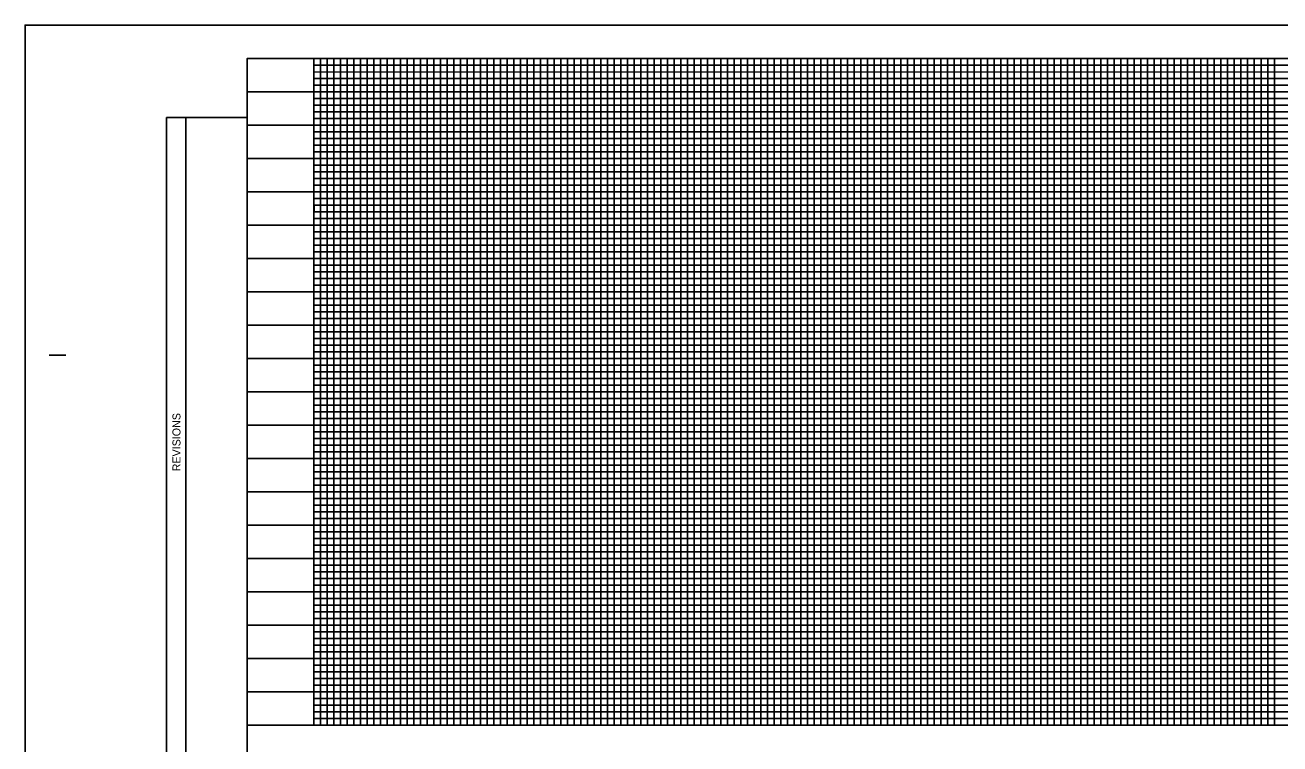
# Model space of a CAD drawing. Extents: x 2431000 to 2534000, y 645879 to 714000.
# Drawn here: x 2466807 to 2467748, y 669403 to 669942 of the extents above; entities that cross this region are included whole.
import ezdxf

# ---------------------------------------------------------------- set-up
doc = ezdxf.new("R2010")
doc.units = 0
for name, color, linetype in [('Prop Dimension', 7, 'Continuous'), ('Prop Shade Light', 7, 'Continuous'), ('Sheet Cross Section CELL', 7, 'Continuous'), ('Sheet Cross Section Grid Major CELL', 7, 'Continuous'), ('Sheet Cross Section Grid Middle CELL', 7, 'Continuous'), ('Sheet North Arrow Point CELL', 7, 'Continuous'), ('Sheet Plan And Profile CELL', 7, 'Continuous')]:
    doc.layers.add(name, color=color, linetype=linetype)

msp = doc.modelspace()

# ---------------------------------------------------------------- linework, layer by layer
at = {"layer": 'Prop Dimension'}
msp.add_lwpolyline([(2466807.25, 668842.06), (2468490.75, 668842.06), (2468490.75, 669942.06), (2466807.25, 669942.06)], close=True, dxfattribs=at)
at = {"layer": 'Prop Shade Light'}
for p, q in [((2466913.23, 669382.06), (2466913.23, 669872.71)), ((2466973.77, 669872.71), (2466913.23, 669872.71)), ((2466927.77, 669382.06), (2466927.77, 669872.72))]:
    msp.add_line(p, q, dxfattribs=at)
at = {"layer": 'Sheet Cross Section CELL'}
for p, q in [((2467023.75, 669912.06), (2468173.75, 669912.06)), ((2467023.75, 669907.06), (2467023.75, 669907.06)), ((2468173.75, 669907.03), (2467023.75, 669906.71)), ((2467023.75, 669902.06), (2468173.75, 669902.06)), ((2468173.75, 669782.06), (2467023.75, 669782.06)), ((2468423.75, 669777.06), (2467023.75, 669777.06)), ((2468423.75, 669772.06), (2467023.75, 669772.06)), ((2467023.75, 669762.06), (2468423.75, 669762.06)), ((2468423.75, 669757.06), (2467023.75, 669757.06)), ((2467023.75, 669752.06), (2468423.75, 669752.06)), ((2468423.75, 669732.06), (2467023.75, 669732.06)), ((2467023.75, 669727.06), (2468423.75, 669727.06)), ((2468423.75, 669707.06), (2467023.75, 669707.06)), ((2467023.75, 669702.06), (2468423.75, 669702.06)), ((2468423.75, 669682.06), (2467023.75, 669682.06)), ((2467023.75, 669677.06), (2468423.75, 669677.06)), ((2468423.75, 669672.06), (2467023.75, 669672.06)), ((2467023.75, 669662.06), (2468423.75, 669662.06)), ((2468423.75, 669657.06), (2467023.75, 669657.06)), ((2467023.75, 669652.06), (2468423.75, 669652.06)), ((2468423.75, 669647.06), (2467023.75, 669647.06)), ((2467023.75, 669637.06), (2468423.75, 669637.06)), ((2468423.75, 669632.06), (2467023.75, 669632.06)), ((2467023.75, 669627.06), (2468423.75, 669627.06)), ((2468423.75, 669622.06), (2467023.75, 669622.06)), ((2467023.75, 669612.06), (2468423.75, 669612.06)), ((2468423.75, 669607.06), (2467023.75, 669607.06)), ((2467023.75, 669602.06), (2468423.75, 669602.06)), ((2468423.75, 669597.06), (2467023.75, 669597.06)), ((2467023.75, 669587.06), (2468423.75, 669587.06)), ((2468423.75, 669582.06), (2467023.75, 669582.06)), ((2467023.75, 669577.06), (2468423.75, 669577.06)), ((2468423.75, 669572.06), (2467023.75, 669572.06)), ((2467023.75, 669562.06), (2468423.75, 669562.06)), ((2468423.75, 669557.06), (2467023.75, 669557.06)), ((2467023.75, 669552.06), (2468423.75, 669552.06)), ((2468423.75, 669547.06), (2467023.75, 669547.06)), ((2467023.75, 669537.06), (2468423.75, 669537.06)), ((2468423.75, 669532.06), (2467023.75, 669532.06)), ((2468423.75, 669527.06), (2467023.75, 669527.06)), ((2468423.75, 669522.06), (2467023.75, 669522.06)), ((2467023.75, 669512.06), (2468423.75, 669512.06)), ((2468423.75, 669507.06), (2467023.75, 669507.06)), ((2467023.75, 669502.06), (2468423.75, 669502.06)), ((2468423.75, 669497.06), (2467023.75, 669497.06)), ((2467023.75, 669487.06), (2468423.75, 669487.06)), ((2468423.75, 669482.06), (2467023.75, 669482.06)), ((2467023.75, 669477.06), (2468423.75, 669477.06)), ((2468423.75, 669472.06), (2467023.75, 669472.06)), ((2467023.75, 669462.06), (2468423.75, 669462.06)), ((2468423.75, 669457.06), (2467023.75, 669457.06)), ((2467023.75, 669452.06), (2468423.75, 669452.06)), ((2468423.75, 669447.06), (2467023.75, 669447.06)), ((2467023.75, 669437.06), (2468423.75, 669437.06)), ((2468423.75, 669432.06), (2467023.75, 669432.06)), ((2467023.75, 669427.06), (2468423.75, 669427.06))]:
    msp.add_line(p, q, dxfattribs=at)
for points in [[(2466973.75, 669417.06), (2468168.75, 669417.06), (2468168.75, 669917.06)], [(2467028.75, 669917.06), (2467028.75, 669417.06), (2467033.75, 669417.06), (2467033.75, 669917.06), (2467038.75, 669917.06), (2467038.75, 669417.06), (2467043.75, 669417.06), (2467043.75, 669917.06), (2467053.75, 669917.06), (2467053.75, 669417.06), (2467058.75, 669417.06), (2467058.75, 669917.06), (2467063.75, 669917.06), (2467063.75, 669417.06), (2467068.75, 669417.06), (2467078.75, 669417.06), (2467083.75, 669417.06), (2467083.75, 669917.06), (2467088.75, 669917.06), (2467088.75, 669417.06), (2467093.75, 669417.06), (2467093.75, 669917.06), (2467103.75, 669917.06), (2467103.75, 669417.06), (2467108.75, 669417.06), (2467108.75, 669917.06), (2467113.75, 669917.06), (2467113.75, 669417.06), (2467118.75, 669417.06), (2467118.75, 669917.06), (2467128.75, 669917.06), (2467128.75, 669417.06), (2467133.75, 669417.06), (2467133.75, 669917.06), (2467138.75, 669917.06), (2467138.75, 669417.06), (2467143.75, 669417.06), (2467143.75, 669917.06), (2467153.75, 669917.06), (2467153.75, 669417.06), (2467158.75, 669417.06), (2467158.75, 669917.06), (2467163.75, 669917.06), (2467163.75, 669417.06), (2467168.75, 669417.06), (2467168.75, 669917.06), (2467178.75, 669917.06), (2467178.75, 669417.06), (2467183.75, 669417.06), (2467183.75, 669917.06), (2467188.75, 669917.06), (2467188.75, 669417.06), (2467193.75, 669417.06), (2467193.75, 669917.06), (2467203.75, 669917.06), (2467203.75, 669417.06), (2467208.75, 669417.06), (2467208.75, 669917.06), (2467213.75, 669917.06), (2467213.75, 669417.06), (2467218.75, 669417.06), (2467218.75, 669917.06), (2467228.75, 669917.06), (2467228.75, 669417.06), (2467233.75, 669417.06), (2467233.75, 669917.06), (2467238.75, 669917.06), (2467238.75, 669417.06)], [(2467068.75, 669417.06), (2467068.75, 669917.06), (2467078.75, 669917.06), (2467078.75, 669417.06)], [(2467238.75, 669417.06), (2467243.75, 669417.06), (2467243.75, 669917.06), (2467253.75, 669917.06), (2467253.75, 669417.06), (2467258.75, 669417.06), (2467258.75, 669917.06), (2467263.75, 669917.06), (2467263.75, 669417.06), (2467268.75, 669417.06), (2467268.75, 669917.06), (2467278.75, 669917.06), (2467278.75, 669417.06), (2467283.75, 669417.06), (2467283.75, 669917.06), (2467288.75, 669917.06), (2467288.75, 669417.06), (2467293.75, 669417.06), (2467293.75, 669917.06), (2467303.75, 669917.06), (2467303.75, 669417.06), (2467308.75, 669417.06), (2467308.75, 669917.06), (2467313.75, 669917.06), (2467313.75, 669417.06), (2467318.75, 669417.06), (2467318.75, 669917.06), (2467328.75, 669917.06), (2467328.75, 669417.06), (2467333.75, 669417.06), (2467333.75, 669917.06), (2467338.75, 669917.06), (2467338.75, 669417.06), (2467343.75, 669417.06), (2467343.75, 669917.06), (2467353.75, 669917.06), (2467353.75, 669417.06), (2467358.75, 669417.06), (2467358.75, 669917.06), (2467363.75, 669917.06), (2467363.75, 669417.06), (2467368.75, 669417.06), (2467368.75, 669917.06), (2467378.75, 669917.06), (2467378.75, 669417.06), (2467383.75, 669417.06), (2467383.75, 669917.06), (2467388.75, 669917.06), (2467388.75, 669417.06), (2467393.75, 669417.06), (2467393.75, 669917.06), (2467403.75, 669917.06), (2467403.75, 669417.06), (2467408.75, 669417.06), (2467408.75, 669917.06), (2467413.75, 669917.06), (2467413.75, 669417.06), (2467418.75, 669417.06), (2467418.75, 669917.06), (2467428.75, 669917.06), (2467428.75, 669417.06), (2467433.75, 669417.06), (2467433.75, 669917.06), (2467438.75, 669917.06), (2467438.75, 669417.06), (2467443.75, 669417.06), (2467443.75, 669917.06), (2467453.75, 669917.06), (2467453.75, 669417.06), (2467458.75, 669417.06), (2467458.75, 669917.06), (2467463.75, 669917.06), (2467463.75, 669417.06), (2467468.75, 669417.06), (2467468.75, 669917.06), (2467478.75, 669917.06), (2467478.75, 669417.06), (2467483.75, 669417.06), (2467483.75, 669917.06), (2467488.75, 669917.06), (2467488.75, 669417.06), (2467493.75, 669417.06), (2467493.75, 669917.06), (2467503.75, 669917.06), (2467503.75, 669417.06), (2467508.75, 669417.06), (2467508.75, 669917.06), (2467513.75, 669917.06), (2467513.75, 669417.06), (2467518.75, 669417.06), (2467518.75, 669917.06), (2467528.75, 669917.06), (2467528.75, 669417.06), (2467533.75, 669417.06), (2467533.75, 669917.06), (2467538.75, 669917.06), (2467538.75, 669417.06), (2467543.75, 669417.06), (2467543.75, 669917.06), (2467553.75, 669917.06)], [(2467553.75, 669917.06), (2467553.75, 669417.06), (2467558.75, 669417.06), (2467558.75, 669917.06), (2467563.75, 669917.06), (2467563.75, 669417.06), (2467568.75, 669417.06), (2467568.75, 669917.06), (2467578.75, 669917.06), (2467578.75, 669417.06), (2467583.75, 669417.06), (2467583.75, 669917.06), (2467588.75, 669917.06), (2467588.75, 669417.06), (2467593.75, 669417.06), (2467593.75, 669917.06), (2467603.75, 669917.06), (2467603.75, 669417.06), (2467608.75, 669417.06), (2467608.75, 669917.06), (2467613.75, 669917.06), (2467613.75, 669417.06), (2467618.75, 669417.06), (2467618.75, 669917.06), (2467628.75, 669917.06), (2467628.75, 669417.06), (2467633.75, 669417.06), (2467633.75, 669917.06), (2467638.75, 669917.06), (2467638.75, 669417.06), (2467643.75, 669417.06), (2467643.75, 669917.06), (2467653.75, 669917.06), (2467653.75, 669417.06), (2467658.75, 669417.06), (2467658.75, 669917.06), (2467663.75, 669917.06), (2467663.75, 669417.06), (2467668.75, 669417.06), (2467668.75, 669917.06), (2467678.75, 669917.06), (2467678.75, 669417.06), (2467678.75, 669417.06), (2467683.75, 669417.06), (2467683.75, 669917.06), (2467688.75, 669917.06), (2467688.75, 669417.06), (2467693.75, 669417.06), (2467693.75, 669917.06), (2467703.75, 669917.06), (2467703.75, 669417.06), (2467708.75, 669417.06), (2467708.75, 669917.06), (2467713.75, 669917.06), (2467713.75, 669417.06), (2467718.75, 669417.06), (2467718.75, 669917.06), (2467728.75, 669917.06), (2467728.75, 669417.06), (2467733.75, 669417.06), (2467733.75, 669917.06), (2467738.75, 669917.06), (2467738.75, 669417.06), (2467743.75, 669417.06), (2467743.75, 669917.06), (2467753.75, 669917.06)], [(2468173.75, 669897.06), (2467023.75, 669897.06), (2467023.75, 669887.06), (2468173.75, 669887.06)], [(2468173.75, 669882.06), (2467023.75, 669882.06), (2467023.75, 669877.06), (2468173.75, 669877.06)], [(2468173.75, 669872.06), (2467023.75, 669872.06), (2467023.75, 669862.06), (2468173.75, 669862.06)], [(2468173.75, 669857.06), (2467023.75, 669857.06), (2467023.75, 669852.06), (2468173.75, 669852.06)], [(2468173.75, 669847.06), (2467023.75, 669847.06), (2467023.75, 669837.06), (2468173.75, 669837.06)], [(2468173.75, 669832.06), (2467023.75, 669832.06), (2467023.75, 669827.06), (2468173.75, 669827.06)], [(2468173.75, 669822.06), (2467023.75, 669822.06), (2467023.75, 669812.06), (2468173.75, 669812.06)], [(2468173.75, 669806.96), (2467023.85, 669806.96), (2467023.85, 669802.06), (2468173.75, 669802.06)], [(2468173.75, 669797.06), (2467023.75, 669797.06), (2467023.75, 669787.06), (2468173.75, 669787.06)], [(2468423.75, 669747.06), (2467023.75, 669747.06), (2467023.75, 669737.06), (2468423.75, 669737.06)], [(2468423.75, 669722.06), (2467023.75, 669722.06), (2467023.75, 669712.06), (2468423.75, 669712.06)], [(2468423.75, 669697.06), (2467023.75, 669697.06), (2467023.75, 669687.06), (2468423.75, 669687.06)], [(2468423.75, 669422.06), (2467023.75, 669422.06)]]:
    msp.add_lwpolyline(points, dxfattribs=at)
at = {"layer": 'Sheet Cross Section Grid Major CELL'}
for points in [[(2467048.75, 669917.06), (2467048.75, 669417.06), (2467098.75, 669417.06), (2467098.75, 669917.06), (2467148.75, 669917.06), (2467148.75, 669417.06), (2467198.75, 669417.06), (2467198.75, 669917.06), (2467248.75, 669917.06), (2467248.75, 669417.06), (2467298.75, 669417.06), (2467298.75, 669917.06), (2467348.75, 669917.06), (2467348.75, 669417.06), (2467398.75, 669417.06), (2467398.75, 669917.06), (2467448.75, 669917.06), (2467448.75, 669417.06), (2467498.75, 669417.06), (2467498.75, 669917.06), (2467548.75, 669917.06), (2467548.75, 669417.06), (2467598.75, 669417.06), (2467598.75, 669417.06), (2467598.75, 669917.06), (2467648.75, 669917.06), (2467648.75, 669417.06), (2467698.75, 669417.06), (2467698.75, 669917.06), (2467748.75, 669917.06)], [(2468173.75, 669842.06), (2466973.75, 669842.06), (2466973.75, 669792.06), (2468173.75, 669792.06)], [(2468473.75, 669742.06), (2466973.75, 669742.06), (2466973.75, 669692.06), (2468298.75, 669692.06)], [(2468473.75, 669642.06), (2466973.75, 669642.06), (2466973.75, 669592.06), (2468473.75, 669592.06)], [(2468473.75, 669542.06), (2466973.75, 669542.06), (2466973.75, 669492.06), (2468473.75, 669492.06)], [(2468473.75, 669442.06), (2466973.75, 669442.06)]]:
    msp.add_lwpolyline(points, dxfattribs=at)
at = {"layer": 'Sheet Cross Section Grid Middle CELL'}
msp.add_lwpolyline([(2468456.5, 669779.51), (2468292.45, 669779.51), (2468292.45, 669917.06), (2467023.75, 669917.06), (2467023.75, 669417.06), (2468423.75, 669417.06), (2468423.75, 669779.51)], dxfattribs=at)
at = {"layer": 'Sheet North Arrow Point CELL'}
msp.add_line((2466973.75, 669892.06), (2468173.75, 669892.06), dxfattribs=at)
for points in [[(2467023.75, 669917.06), (2467023.75, 669417.06), (2467073.75, 669417.06), (2467073.75, 669917.06), (2467123.75, 669917.06), (2467123.75, 669417.06), (2467173.75, 669417.06), (2467173.75, 669917.06), (2467223.75, 669917.06), (2467223.75, 669417.06), (2467273.75, 669417.06), (2467273.75, 669917.06), (2467323.75, 669917.06), (2467323.75, 669417.06), (2467373.75, 669417.06), (2467373.75, 669917.06), (2467423.75, 669917.06), (2467423.75, 669417.06), (2467473.75, 669417.06), (2467473.75, 669917.06), (2467523.75, 669917.06), (2467523.75, 669417.06), (2467573.75, 669417.06), (2467573.75, 669917.06), (2467623.75, 669917.06), (2467623.75, 669417.06), (2467673.75, 669417.06), (2467673.75, 669917.06), (2467723.75, 669917.06), (2467723.75, 669417.06), (2467773.75, 669417.06)], [(2466973.75, 669867.06), (2468173.75, 669867.06)], [(2468173.75, 669817.06), (2466973.75, 669817.06), (2466973.75, 669767.06), (2468473.75, 669767.06)], [(2468473.75, 669717.06), (2466973.75, 669717.06), (2466973.75, 669667.06), (2468473.75, 669667.06)], [(2468473.75, 669617.06), (2466973.75, 669617.06), (2466973.75, 669567.06), (2468473.75, 669567.06)], [(2468473.75, 669517.06), (2466973.75, 669517.06), (2466973.75, 669517.06), (2466973.75, 669467.06), (2468473.75, 669467.06)]]:
    msp.add_lwpolyline(points, dxfattribs=at)
at = {"layer": 'Sheet Plan And Profile CELL'}
for p, q in [((2466825.25, 669694.56), (2466837.75, 669694.56)), ((2466973.75, 669417.06), (2468473.75, 669417.06)), ((2466973.75, 669417.06), (2468473.75, 669417.06))]:
    msp.add_line(p, q, dxfattribs=at)
msp.add_lwpolyline([(2468473.75, 669917.06), (2466973.75, 669917.06), (2466973.75, 668867.06), (2468473.75, 668867.06)], close=True, dxfattribs=at)

# ---------------------------------------------------------------- texts
at = {"layer": 'Prop Shade Light'}
msp.add_text('REVISIONS', height=6, rotation=90, dxfattribs=at).set_placement((2466923.73, 669607.45))

doc.saveas('drawing.dxf')
